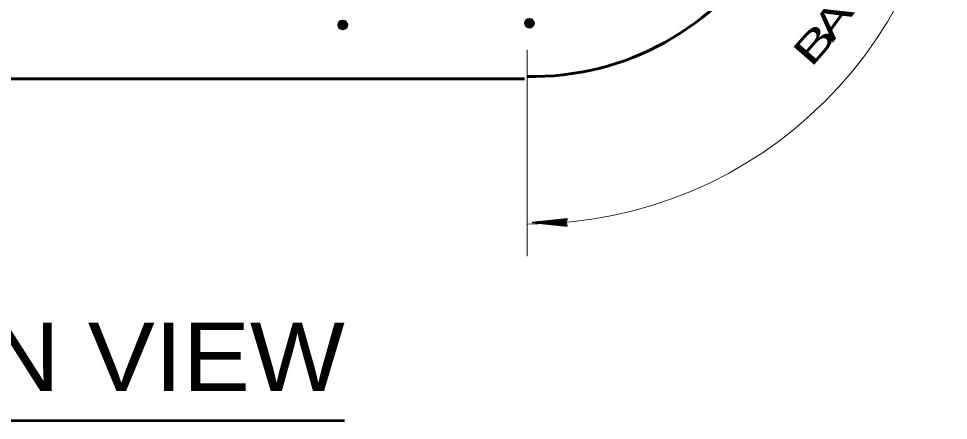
# Model space of a CAD drawing. Extents: x 3.64 to 6.84, y -0.8 to 1.19.
# Drawn here: x 4.3787 to 4.6619, y 0.598 to 0.7205 of the extents above; entities that cross this region are included whole.
import ezdxf

# ---------------------------------------------------------------- set-up
doc = ezdxf.new("R2010")
doc.units = 0
doc.header["$LTSCALE"] = 0.0033
doc.layers.add('1', color=7, linetype='Continuous', lineweight=40)

msp = doc.modelspace()

# ---------------------------------------------------------------- linework, layer by layer
at = {"layer": '1'}
for p, q in [((4.476583, 0.7195), (4.4785, 0.719167)), ((4.476583, 0.7195), (4.4785, 0.719167)), ((4.533667, 0.72025), (4.533333, 0.71825)), ((4.53375, 0.720167), (4.533417, 0.71825)), ((4.533833, 0.720167), (4.5335, 0.71825)), ((4.533917, 0.720167), (4.533583, 0.718167)), ((4.535083, 0.72), (4.533583, 0.720083)), ((4.535083, 0.719917), (4.533583, 0.72)), ((4.535083, 0.719833), (4.533583, 0.719917)), ((4.535083, 0.71975), (4.533583, 0.719833)), ((4.535083, 0.719667), (4.533583, 0.71975)), ((4.535083, 0.7195), (4.533583, 0.719583)), ((4.535083, 0.719417), (4.533583, 0.7195)), ((4.535083, 0.719333), (4.533583, 0.719417)), ((4.534167, 0.720167), (4.53375, 0.718167)), ((4.534333, 0.720083), (4.533917, 0.718167)), ((4.534417, 0.720083), (4.534, 0.718167)), ((4.5345, 0.720083), (4.534083, 0.718083)), ((4.534583, 0.720083), (4.53425, 0.718083)), ((4.534667, 0.72), (4.534333, 0.718083)), ((4.534833, 0.72), (4.534417, 0.718)), ((4.534917, 0.72), (4.5345, 0.718)), ((4.535, 0.72), (4.534667, 0.718)), ((4.535083, 0.72), (4.53475, 0.718)), ((4.53525, 0.719917), (4.534917, 0.718)), ((4.47625, 0.717917), (4.47825, 0.717583)), ((4.47625, 0.717917), (4.47825, 0.717583)), ((4.476333, 0.718417), (4.478333, 0.718)), ((4.476333, 0.718417), (4.478333, 0.718)), ((4.476333, 0.718167), (4.478333, 0.717833)), ((4.476333, 0.718167), (4.478333, 0.717833)), ((4.476333, 0.718083), (4.47825, 0.71775)), ((4.476333, 0.718083), (4.47825, 0.71775)), ((4.476333, 0.718), (4.47825, 0.717667)), ((4.476333, 0.718), (4.47825, 0.717667)), ((4.4765, 0.719333), (4.476417, 0.717833)), ((4.4765, 0.719333), (4.476417, 0.717833)), ((4.476417, 0.718833), (4.478417, 0.7185)), ((4.476417, 0.718833), (4.478417, 0.7185)), ((4.476417, 0.71875), (4.478417, 0.718333)), ((4.476417, 0.71875), (4.478417, 0.718333)), ((4.476417, 0.718667), (4.478333, 0.71825)), ((4.476417, 0.718667), (4.478333, 0.71825)), ((4.476417, 0.718583), (4.478333, 0.718167)), ((4.476417, 0.718583), (4.478333, 0.718167)), ((4.476583, 0.719333), (4.4765, 0.717833)), ((4.4765, 0.719333), (4.4785, 0.719)), ((4.476583, 0.719333), (4.4765, 0.717833)), ((4.4765, 0.719333), (4.4785, 0.719)), ((4.4765, 0.71925), (4.4785, 0.718917)), ((4.4765, 0.71925), (4.4785, 0.718917)), ((4.4765, 0.719167), (4.4785, 0.71875)), ((4.4765, 0.719167), (4.4785, 0.71875)), ((4.4765, 0.719083), (4.4785, 0.718667)), ((4.4765, 0.719083), (4.4785, 0.718667)), ((4.4765, 0.718917), (4.478417, 0.718583)), ((4.4765, 0.718917), (4.478417, 0.718583)), ((4.476667, 0.719333), (4.476583, 0.717833)), ((4.476667, 0.719333), (4.476583, 0.717833)), ((4.47675, 0.719333), (4.476667, 0.717833)), ((4.47675, 0.719333), (4.476667, 0.717833)), ((4.476833, 0.719333), (4.47675, 0.717833)), ((4.476833, 0.719333), (4.47675, 0.717833)), ((4.477, 0.719333), (4.476917, 0.717833)), ((4.477, 0.719333), (4.476917, 0.717833)), ((4.477083, 0.719333), (4.477, 0.717833)), ((4.477083, 0.719333), (4.477, 0.717833)), ((4.477167, 0.719333), (4.477083, 0.717833)), ((4.477167, 0.719333), (4.477083, 0.717833)), ((4.47725, 0.719333), (4.477167, 0.717833)), ((4.47725, 0.719333), (4.477167, 0.717833)), ((4.477333, 0.719333), (4.47725, 0.717833)), ((4.477333, 0.719333), (4.47725, 0.717833)), ((4.477417, 0.719333), (4.477333, 0.717833)), ((4.477417, 0.719333), (4.477333, 0.717833)), ((4.4775, 0.719333), (4.477417, 0.717833)), ((4.4775, 0.719333), (4.477417, 0.717833)), ((4.477667, 0.71925), (4.4775, 0.71775)), ((4.477667, 0.71925), (4.4775, 0.71775)), ((4.477833, 0.71925), (4.477667, 0.71775)), ((4.477833, 0.71925), (4.477667, 0.71775)), ((4.477917, 0.71925), (4.477833, 0.71775)), ((4.477917, 0.71925), (4.477833, 0.71775)), ((4.477917, 0.71925), (4.477833, 0.71775)), ((4.477917, 0.71925), (4.477833, 0.71775)), ((4.478, 0.71925), (4.477917, 0.71775)), ((4.478, 0.71925), (4.477917, 0.71775)), ((4.478083, 0.71925), (4.478, 0.71775)), ((4.478083, 0.71925), (4.478, 0.71775)), ((4.478167, 0.71925), (4.478083, 0.71775)), ((4.478167, 0.71925), (4.478083, 0.71775)), ((4.47825, 0.71925), (4.478167, 0.71775)), ((4.47825, 0.71925), (4.478167, 0.71775)), ((4.478333, 0.71925), (4.47825, 0.71775)), ((4.478333, 0.71925), (4.47825, 0.71775)), ((4.478417, 0.71925), (4.478333, 0.71775)), ((4.478417, 0.71925), (4.478333, 0.71775)), ((4.478583, 0.71925), (4.4785, 0.71775)), ((4.478583, 0.71925), (4.4785, 0.71775)), ((4.535, 0.718833), (4.5335, 0.719)), ((4.535, 0.718667), (4.5335, 0.718833)), ((4.535, 0.718583), (4.5335, 0.718667)), ((4.535, 0.718583), (4.5335, 0.718667)), ((4.535, 0.7185), (4.5335, 0.718583)), ((4.535, 0.718417), (4.5335, 0.7185)), ((4.535, 0.718333), (4.5335, 0.718417)), ((4.535, 0.71825), (4.5335, 0.718333)), ((4.535, 0.718167), (4.5335, 0.71825)), ((4.535, 0.718083), (4.5335, 0.718167)), ((4.535, 0.717917), (4.5335, 0.718)), ((4.535083, 0.71925), (4.533583, 0.719333)), ((4.535083, 0.719167), (4.533583, 0.71925)), ((4.535083, 0.719083), (4.533583, 0.719167)), ((4.535083, 0.719), (4.533583, 0.719083))]:
    msp.add_line(p, q, dxfattribs=at)
at = {"layer": '1', "lineweight": 13}
msp.add_line((4.533583, 0.648083), (4.533583, 0.711), dxfattribs=at)
at = {"layer": '1', "lineweight": 60}
for p, q in [((4.49, 0.702083), (4.17625, 0.702083)), ((4.53275, 0.702083), (4.393, 0.702083))]:
    msp.add_line(p, q, dxfattribs=at)
at = {"layer": '1', "lineweight": 35}
for p, q in [((4.54575, 0.658333), (4.535167, 0.658333)), ((4.5455, 0.6575), (4.537667, 0.6585)), ((4.5455, 0.6575), (4.537667, 0.658333)), ((4.5455, 0.657333), (4.537667, 0.65825)), ((4.5455, 0.657333), (4.537667, 0.65825)), ((4.5455, 0.657417), (4.537667, 0.65825)), ((4.5455, 0.659417), (4.538167, 0.658583)), ((4.5455, 0.65925), (4.538167, 0.6585)), ((4.5455, 0.659167), (4.538167, 0.658333)), ((4.545583, 0.659), (4.53825, 0.65825))]:
    msp.add_line(p, q, dxfattribs=at)
at = {"layer": '1', "lineweight": 53}
msp.add_line((4.206167, 0.598), (4.478, 0.598), dxfattribs=at)
at = {"layer": '1'}
for points in [[(4.476083, 0.7185), (4.478667, 0.718833), (4.476333, 0.719333), (4.478667, 0.71825), (4.47625, 0.717833), (4.47825, 0.7175), (4.47825, 0.719583), (4.477333, 0.71725), (4.477583, 0.719833), (4.476583, 0.7175), (4.476917, 0.719833), (4.47775, 0.71725), (4.476167, 0.719), (4.478583, 0.719167), (4.476917, 0.717333), (4.478, 0.71975), (4.476333, 0.719333), (4.47625, 0.717833), (4.477333, 0.71725), (4.47825, 0.7175), (4.478667, 0.71825), (4.478583, 0.719167), (4.478, 0.71975), (4.477333, 0.718667), (4.4785, 0.71775), (4.476583, 0.7175), (4.477333, 0.718667), (4.47625, 0.719167), (4.47725, 0.719833), (4.477333, 0.71875), (4.478167, 0.7175), (4.476167, 0.71875), (4.4775, 0.719083), (4.47825, 0.719583)], [(4.476083, 0.7185), (4.478667, 0.718833), (4.476333, 0.719333), (4.478667, 0.71825), (4.47625, 0.717833), (4.47825, 0.7175), (4.47825, 0.719583), (4.477333, 0.71725), (4.477583, 0.719833), (4.476583, 0.7175), (4.476917, 0.719833), (4.47775, 0.71725), (4.476167, 0.719), (4.478583, 0.719167), (4.476917, 0.717333), (4.478, 0.71975), (4.476333, 0.719333), (4.47625, 0.717833), (4.477333, 0.71725), (4.47825, 0.7175), (4.478667, 0.71825), (4.478583, 0.719167), (4.478, 0.71975), (4.477333, 0.718667), (4.4785, 0.71775), (4.476583, 0.7175), (4.477333, 0.718667), (4.47625, 0.719167), (4.47725, 0.719833), (4.477333, 0.71875), (4.478167, 0.7175), (4.476167, 0.71875), (4.4775, 0.719083), (4.47825, 0.719583)], [(4.53425, 0.720417), (4.534583, 0.717833), (4.535083, 0.720167), (4.534, 0.717833), (4.533583, 0.72025), (4.53325, 0.71825), (4.535333, 0.71825), (4.533, 0.719167), (4.535583, 0.718917), (4.53325, 0.719917), (4.535583, 0.719583), (4.533, 0.71875), (4.53475, 0.720333), (4.534917, 0.717917), (4.533083, 0.719583), (4.5355, 0.7185), (4.535083, 0.720167), (4.533583, 0.72025), (4.533, 0.719167), (4.53325, 0.71825), (4.534, 0.717833), (4.534917, 0.717917), (4.5355, 0.7185), (4.534417, 0.719167), (4.5335, 0.718), (4.53325, 0.719917), (4.534417, 0.719167), (4.534917, 0.72025), (4.535583, 0.71925), (4.5345, 0.719167), (4.53325, 0.718333), (4.5345, 0.720333), (4.534833, 0.719), (4.535333, 0.71825)]]:
    msp.add_lwpolyline(points, dxfattribs=at)
at = {"layer": '1', "lineweight": 35}
for points in [[(4.54575, 0.65725), (4.535167, 0.658333), (4.54575, 0.6595), (4.545167, 0.658333)], [(4.545, 0.65825), (4.540333, 0.658167), (4.540333, 0.65825), (4.54125, 0.65825), (4.545, 0.658167), (4.542, 0.658083), (4.545167, 0.658), (4.542917, 0.657917), (4.545167, 0.657833), (4.541667, 0.658083), (4.537, 0.65825), (4.537917, 0.6585), (4.536667, 0.6585), (4.545, 0.6585), (4.542583, 0.658667), (4.545167, 0.658667), (4.539833, 0.65825), (4.545167, 0.658917)]]:
    msp.add_lwpolyline(points, close=True, dxfattribs=at)
msp.add_lwpolyline([(4.545, 0.65825), (4.545417, 0.6575), (4.545167, 0.65775), (4.545, 0.658083), (4.54475, 0.658), (4.544917, 0.657667), (4.545083, 0.658417), (4.54525, 0.658917), (4.5455, 0.659333)], dxfattribs=at)
at = {"layer": '1'}
for centre in [(4.477417, 0.71855), (4.477417, 0.71855), (4.5343, 0.719083)]:
    msp.add_circle(centre, 0.00132, dxfattribs=at)
at = {"layer": '1', "lineweight": 13}
msp.add_arc((4.533833, 0.785917), 0.128083, 270, 90, dxfattribs=at)
at = {"layer": '1', "lineweight": 60}
msp.add_arc((4.535333, 0.785667), 0.082833, 268.75109, 90.47945, dxfattribs=at)

# ---------------------------------------------------------------- texts
at = {"layer": '1'}
for s, height, rotation, width, p in [('A', 0.008333, 53.842, 1.55, (4.626667, 0.713083)), ('B', 0.008334, 48.731, 1.7, (4.62, 0.70525))]:
    msp.add_text(s, height=height, rotation=rotation, dxfattribs=dict(at, width=width)).set_placement(p)
at = {"layer": '1', "width": 1.1}
msp.add_text('STEM PLAN VIEW', height=0.02083, dxfattribs=at).set_placement((4.217583, 0.607))

doc.saveas('drawing.dxf')
